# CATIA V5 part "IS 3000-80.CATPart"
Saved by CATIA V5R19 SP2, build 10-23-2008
Part number: IS 3000-80
Bounding box of the stored display mesh (mm): x -47.487 to 47.487, y -47.487 to 47.487, z 0 to 280
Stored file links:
  C:\Users\Bora\Desktop\3D Katı model\IS serisi\IS 3000\IS 3000-80.CATPart
  C:\Program Files\Dassault Systemes\B19\intel_a\reffiles\standard\MetricThickPitch.txt
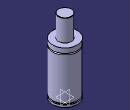
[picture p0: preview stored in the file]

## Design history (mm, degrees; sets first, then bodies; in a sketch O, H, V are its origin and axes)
Body1 (main body)
  Sketch1 on yz-plane, origin (0, 0, 0), H (0, 1, 0), V (0, 0, 1)
    point P1 (47.5, 178.5)
    point P2 (47.5, 173.5)
    point P5 (25, 279)
    point P7 (25, 279)
    point P12 (47.5, 173.5)
    point P13 (47.5, 178.5)
    arc A1 centre (47.5, 176) radius 2.5 from (47.5, 178.5) to (47.5, 173.5) ccw
    line L1 (47.5, 0) -> (47.5, 8)
    line L2 (25, 279) -> (25, 197)
    arc A2 centre (24, 279) radius 1 from (25, 279) to (24, 280) ccw
    line L3 (43.5, 13) -> (43.5, 8)
    line L4 (47.5, 13) -> (47.5, 173.5)
    line L5 (47.5, 178.5) -> (47.5, 197)
    line L6 (0, 0) -> (47.5, 0)
    line L7 (43.5, 8) -> (47.5, 8)
    line L8 (43.5, 13) -> (47.5, 13)
    line L9 (25, 197) -> (47.5, 197)
    line L10 (24, 280) -> (0, 280)
    point P15 (0, 280)
    horizontal: L6 H, L7 H, L9 H
    parallelism: L8 L6
    coincidence: P15 V, P1 P13, P2 P12, P5 P7
    tangency: L10 A2
  Shaft1: profile Sketch1, axis Sketch1.V, angle 360
  Sketch2 on face of Shaft1 from Sketch1.L6, origin (0, 0, 0), H (1, 0, 0), V (0, -1, 0)
    point P1 (30, 0)
    distance P1 V = 30
  Hole1: placed by Sketch2, at (30, 0, 0) direction (0, 0, 1), diameter 6.647, depth 13, threaded "M8", thread diameter 8, thread depth 13, pitch 1.25
  CircPattern1: of Hole1, instances 4, angular step 90, axis from xy-plane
